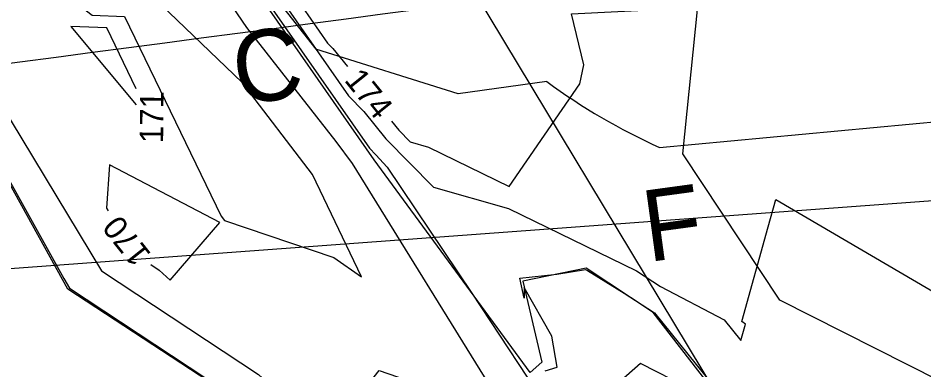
# Model space of a CAD drawing. Extents: x 2086416 to 2115205, y 575507 to 632762.
# Drawn here: x 2111557.3 to 2111634.8, y 581599.4 to 581629.5 of the extents above; entities that cross this region are included whole.
import ezdxf

# ---------------------------------------------------------------- set-up
doc = ezdxf.new("R2010")
doc.units = 0
for name, color, linetype in [('DTM Contours Major', 7, 'Continuous'), ('DTM Contours Major Text', 7, 'Continuous'), ('DTM Contours Minor', 7, 'Continuous'), ('DTM Contours Minor Text', 7, 'Continuous'), ('Exist Hydro Stream or Body of Water', 7, 'Continuous'), ('Exist Hydrographic FEMA Cross Section', 7, 'Continuous'), ('Exist Hydrographic Stream Bed', 7, 'Continuous'), ('Exist Right of Way Line', 7, 'Continuous'), ('Exist Vegetation Woods Line', 7, 'Continuous'), ('Prop SS Cut Line', 7, 'Continuous'), ('Prop SS Cut Text', 7, 'Continuous'), ('Prop SS Fill Line', 7, 'Continuous'), ('Prop SS Fill Text', 7, 'Continuous')]:
    doc.layers.add(name, color=color, linetype=linetype)

msp = doc.modelspace()

# ---------------------------------------------------------------- linework, layer by layer
at = {"layer": 'DTM Contours Major'}
for points in [[(2111561.972, 581631.067), (2111563.648, 581629.772), (2111566.428, 581629.67), (2111574.697, 581612.578), (2111574.966, 581612.195), (2111584.328, 581609.029), (2111586.691, 581607.388), (2111582.492, 581616.152), (2111576.474, 581624.007), (2111569.516, 581630.68), (2111565.57, 581640.043), (2111563.624, 581644.535)], [(2111574.57, 581612.037), (2111565.123, 581616.972), (2111564.883, 581613.251), (2111565.01, 581613.042)], [(2111568.67, 581608.441), (2111569.387, 581607.967), (2111570.316, 581607.11), (2111574.57, 581612.037)]]:
    msp.add_lwpolyline(points, dxfattribs=at)
at = {"layer": 'DTM Contours Minor'}
for points in [[(2111569.01, 581685.022), (2111568.855, 581679.129), (2111567.524, 581675.529), (2111566.521, 581672.948), (2111566.517, 581672.953), (2111566.487, 581672.949), (2111566.146, 581672.893), (2111566.179, 581672.67), (2111567.876, 581660.82), (2111569.433, 581651.069), (2111570.282, 581645.327), (2111570.08, 581645.043), (2111570.701, 581641.072), (2111571.384, 581641.115), (2111571.433, 581641.123), (2111571.418, 581641.253), (2111573.276, 581638.936), (2111576.945, 581633.496), (2111581.656, 581630.446), (2111583.793, 581627.386), (2111584.244, 581626.917), (2111585.478, 581625.384)], [(2111598.535, 581596.664), (2111585.912, 581617.09), (2111584.535, 581618.974), (2111576.895, 581628.719), (2111574.477, 581632.249), (2111572.617, 581634.865), (2111572.402, 581634.572), (2111567.467, 581643.071), (2111567.127, 581645.256), (2111563.317, 581651.146), (2111560.505, 581656.601), (2111559.492, 581657.643), (2111559.123, 581658.446), (2111557.832, 581661.464), (2111555.517, 581665.512)], [(2111589.242, 581620.711), (2111589.877, 581619.921), (2111590.857, 581618.927), (2111592.405, 581618.486), (2111599.33, 581615.104), (2111605.372, 581623.887), (2111605.711, 581625.528), (2111604.66, 581629.897), (2111612.584, 581630.28), (2111613.262, 581630.394), (2111619.383, 581630.749), (2111621.024, 581630.789), (2111642.89, 581633.662), (2111647.196, 581633.15), (2111648.463, 581631.541), (2111653.203, 581633.039), (2111670.864, 581631.971), (2111682.196, 581631.349), (2111685.064, 581615.457), (2111702.133, 581615.465), (2111706.656, 581602.934), (2111726.967, 581593.524), (2111719.652, 581583.63), (2111725.706, 581574.006)], [(2111577.85, 581632.764), (2111579.379, 581631.774), (2111585.586, 581622.885), (2111586.895, 581621.522), (2111588.77, 581619.193), (2111592.833, 581615.071), (2111599.247, 581613.245), (2111610.211, 581607.891), (2111612.256, 581606.571), (2111617.699, 581603.706), (2111619.118, 581601.942), (2111619.518, 581603.35), (2111619.215, 581603.582), (2111621.458, 581611.664), (2111622.113, 581614.012), (2111639.991, 581603.538), (2111640.806, 581603.356), (2111642.077, 581602.394), (2111666.164, 581595.53), (2111674.849, 581575.034)], [(2111578.656, 581630.876), (2111587.378, 581618.383), (2111587.912, 581617.828), (2111588.893, 581616.777), (2111596.136, 581605.984), (2111600.862, 581598.818)], [(2111549.076, 581629.046), (2111561.223, 581607.233), (2111561.714, 581606.423), (2111583.6, 581591.952)], [(2111564.907, 581628.675), (2111561.823, 581628.789), (2111567.42, 581622.114)], [(2111567.432, 581623.456), (2111564.907, 581628.675)], [(2111554.709, 581624.016), (2111564.464, 581607.913), (2111577.893, 581599.034), (2111583.638, 581593.739), (2111584.898, 581595.198), (2111588.199, 581599.364), (2111591.322, 581598.308), (2111596.722, 581594.559), (2111601.884, 581589.387), (2111596.716, 581584.75), (2111593.839, 581583.381), (2111596.471, 581577.936), (2111597.156, 581577.871), (2111597.782, 581578.108), (2111601.297, 581579.615), (2111610.432, 581583.11), (2111617.158, 581580.006), (2111619.199, 581579.456), (2111621.973, 581579.688), (2111624.614, 581575.967), (2111631.966, 581571.272), (2111632.126, 581570.827), (2111633.368, 581570.96)], [(2111602.404, 581599.34), (2111603.418, 581599.672), (2111602.97, 581602.317), (2111600.599, 581606.491), (2111600.592, 581605.568), (2111600.223, 581607.27), (2111603.388, 581607.617), (2111605.834, 581608.022), (2111606.011, 581607.938), (2111609.15, 581605.984), (2111611.652, 581604.369), (2111611.759, 581604.313), (2111620.889, 581592.967)], [(2111614.67, 581597.854), (2111610.553, 581599.981), (2111607.926, 581597.666)]]:
    msp.add_lwpolyline(points, dxfattribs=at)
at = {"layer": 'Exist Hydro Stream or Body of Water'}
for points in [[(2111591.587, 581574.691), (2111583.513, 581582.318), (2111586.645, 581587.276), (2111586.904, 581588.764), (2111586.51, 581589.985), (2111561.568, 581606.344), (2111549.003, 581629.07), (2111542.467, 581641.26), (2111541.348, 581641.183), (2111528.816, 581652.894), (2111524.362, 581663.908), (2111523.315, 581667.748), (2111502.682, 581682.779), (2111481.94, 581698.457), (2111468.579, 581724.282), (2111462.999, 581737.482)], [(2111621.041, 581592.195), (2111611.64, 581604.325), (2111605.912, 581608.14), (2111600.475, 581607.014), (2111602.119, 581600.097), (2111601.107, 581599.205), (2111587.776, 581617.384), (2111576.692, 581633.341), (2111571.484, 581641.081), (2111570.636, 581641.029), (2111569.871, 581645.923), (2111561.21, 581659.642), (2111560.398, 581669.08), (2111561.77, 581674.655), (2111567.139, 581693.151), (2111571.775, 581696.534), (2111557.095, 581714.198)]]:
    msp.add_lwpolyline(points, dxfattribs=at)
at = {"layer": 'Exist Hydrographic FEMA Cross Section'}
msp.add_lwpolyline([(2112201.875, 581700.225), (2111922.666, 581647.707), (2111776.129, 581636.496), (2111658.777, 581615.589), (2111477.281, 581602.232)], dxfattribs=at)
at = {"layer": 'Exist Hydrographic Stream Bed'}
msp.add_lwpolyline([(2112129.652, 582477.712), (2111835.899, 582368.961), (2111727.147, 582231.15), (2111672.647, 582129.589), (2111610.896, 582009.957), (2111585.646, 581897.526), (2111574.646, 581806.895), (2111574.646, 581727.084), (2111582.896, 581679.524), (2111589.146, 581643.704), (2111621.896, 581589.333), (2111665.397, 581516.772), (2111701.647, 581379.011), (2111737.898, 581248.45), (2111785.148, 581103.388)], dxfattribs=at)
at = {"layer": 'Exist Right of Way Line'}
msp.add_arc((2108326.546, 606231.499), 24816.937, 277.3939111, 277.8562149, dxfattribs=at)
at = {"layer": 'Exist Vegetation Woods Line'}
msp.add_lwpolyline([(2111779.567, 581491.973), (2111763.785, 581504.851), (2111745.339, 581525.059), (2111717.304, 581555.588), (2111690.346, 581575.953), (2111665.09, 581587.143), (2111644.347, 581594.336), (2111622.456, 581605.396), (2111614.175, 581617.919), (2111615.41, 581630.255), (2111644.692, 581636.018), (2111711.675, 581643.899), (2111763.228, 581655.57), (2111785.51, 581656)], dxfattribs=at)
at = {"layer": 'Prop SS Cut Line'}
for p, q in [((2111571.503, 581641.14), (2111582.793, 581626.876)), ((2111594.945, 581623.048), (2111582.793, 581626.876)), ((2111602.546, 581624.086), (2111594.945, 581623.048))]:
    msp.add_line(p, q, dxfattribs=at)
at = {"layer": 'Prop SS Fill Line'}
msp.add_line((2111612.182, 581618.45), (2111675.829, 581624.419), dxfattribs=at)
msp.add_arc((2111634.217, 581667.184), 53.484, 233.6904, 245.67051, dxfattribs=at)

# ---------------------------------------------------------------- texts
at = {"layer": 'DTM Contours Major Text'}
msp.add_text('170', height=2, rotation=128.50068, dxfattribs=at).set_placement((2111568.763, 581609.318))
at = {"layer": 'DTM Contours Minor Text'}
for s, rotation, p in [('174', 308.84383, (2111585.154, 581624.192)), ('171', 89.46087, (2111569.721, 581618.809))]:
    msp.add_text(s, height=2, rotation=rotation, dxfattribs=at).set_placement(p)
at = {"layer": 'Prop SS Cut Text'}
msp.add_text('C', height=6.104, rotation=7.77101, dxfattribs=at).set_placement((2111576.103, 581622.068))
at = {"layer": 'Prop SS Fill Text'}
msp.add_text('F', height=6.104, rotation=7.77101, dxfattribs=at).set_placement((2111611.201, 581608.646))

doc.saveas('drawing.dxf')
